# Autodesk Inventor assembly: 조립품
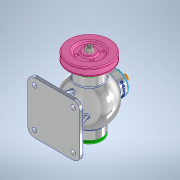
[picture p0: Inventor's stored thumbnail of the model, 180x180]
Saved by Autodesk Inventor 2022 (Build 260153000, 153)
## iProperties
Created: 2024-04
Part Number: 조립품
Document SubType Name: Assembly
Designer: Admin
Author: Admin
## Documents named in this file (16)
- C:\Users\Admin\Desktop\740406V1005\조립품.iam
- C:\Users\Admin\Desktop\740406V1005\본체.ipt
- C:\Users\Admin\Desktop\740406V1005\뒤커버.ipt
- C:\Users\Admin\Desktop\740406V1005\앞커버.ipt
- C:\Users\Admin\Desktop\740406V1005\상부커버.ipt
- C:\Users\Admin\Desktop\740406V1005\베어링- 6202.ipt
- KS B 2023 - 6202 - 15 x 35 x 11 - 7.8.ipt
- C:\Users\Admin\Desktop\740406V1005\칼라.ipt
- C:\Users\Admin\Desktop\740406V1005\편심축.ipt
- C:\Users\Admin\Desktop\740406V1005\키 4 x 4 x 12.ipt
- C:\Users\Admin\Desktop\740406V1005\오일실 15 30 7.ipt
- C:\Users\Admin\Desktop\740406V1005\V-벨트풀리.ipt
- C:\Users\Admin\Desktop\740406V1005\너트 M8.ipt
- C:\Users\Admin\Desktop\740406V1005\볼트 M4 x 16.ipt
- C:\Users\Admin\Desktop\740406V1005\볼트 M4 x 12.ipt
- C:\Users\Admin\Desktop\740406V1005\슬라이드.ipt
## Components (15 placed, 4 different names)
1. KS B 2023 - 6202 - 15 x 35 x 11 - 7.8:1
2. KS B 2023 - 6202 - 15 x 35 x 11 - 7.8:2
3. V-벨트풀리:1
4. ISO 4762 M4 x 16:1
5. ISO 4762 M4 x 16:2
6. ISO 4762 M4 x 16:3
7. ISO 4762 M4 x 16:4
8. ISO 4762 M4 x 16:5
9. ISO 4762 M4 x 16:6
10. ISO 4762 M4 x 16:7
11. ISO 4762 M4 x 16:8
12. KS B 1021 - 에 따름 ISO 1207 - 미터 A  M 4 x 12:1
13. KS B 1021 - 에 따름 ISO 1207 - 미터 A  M 4 x 12:2
14. KS B 1021 - 에 따름 ISO 1207 - 미터 A  M 4 x 12:3
15. KS B 1021 - 에 따름 ISO 1207 - 미터 A  M 4 x 12:4
